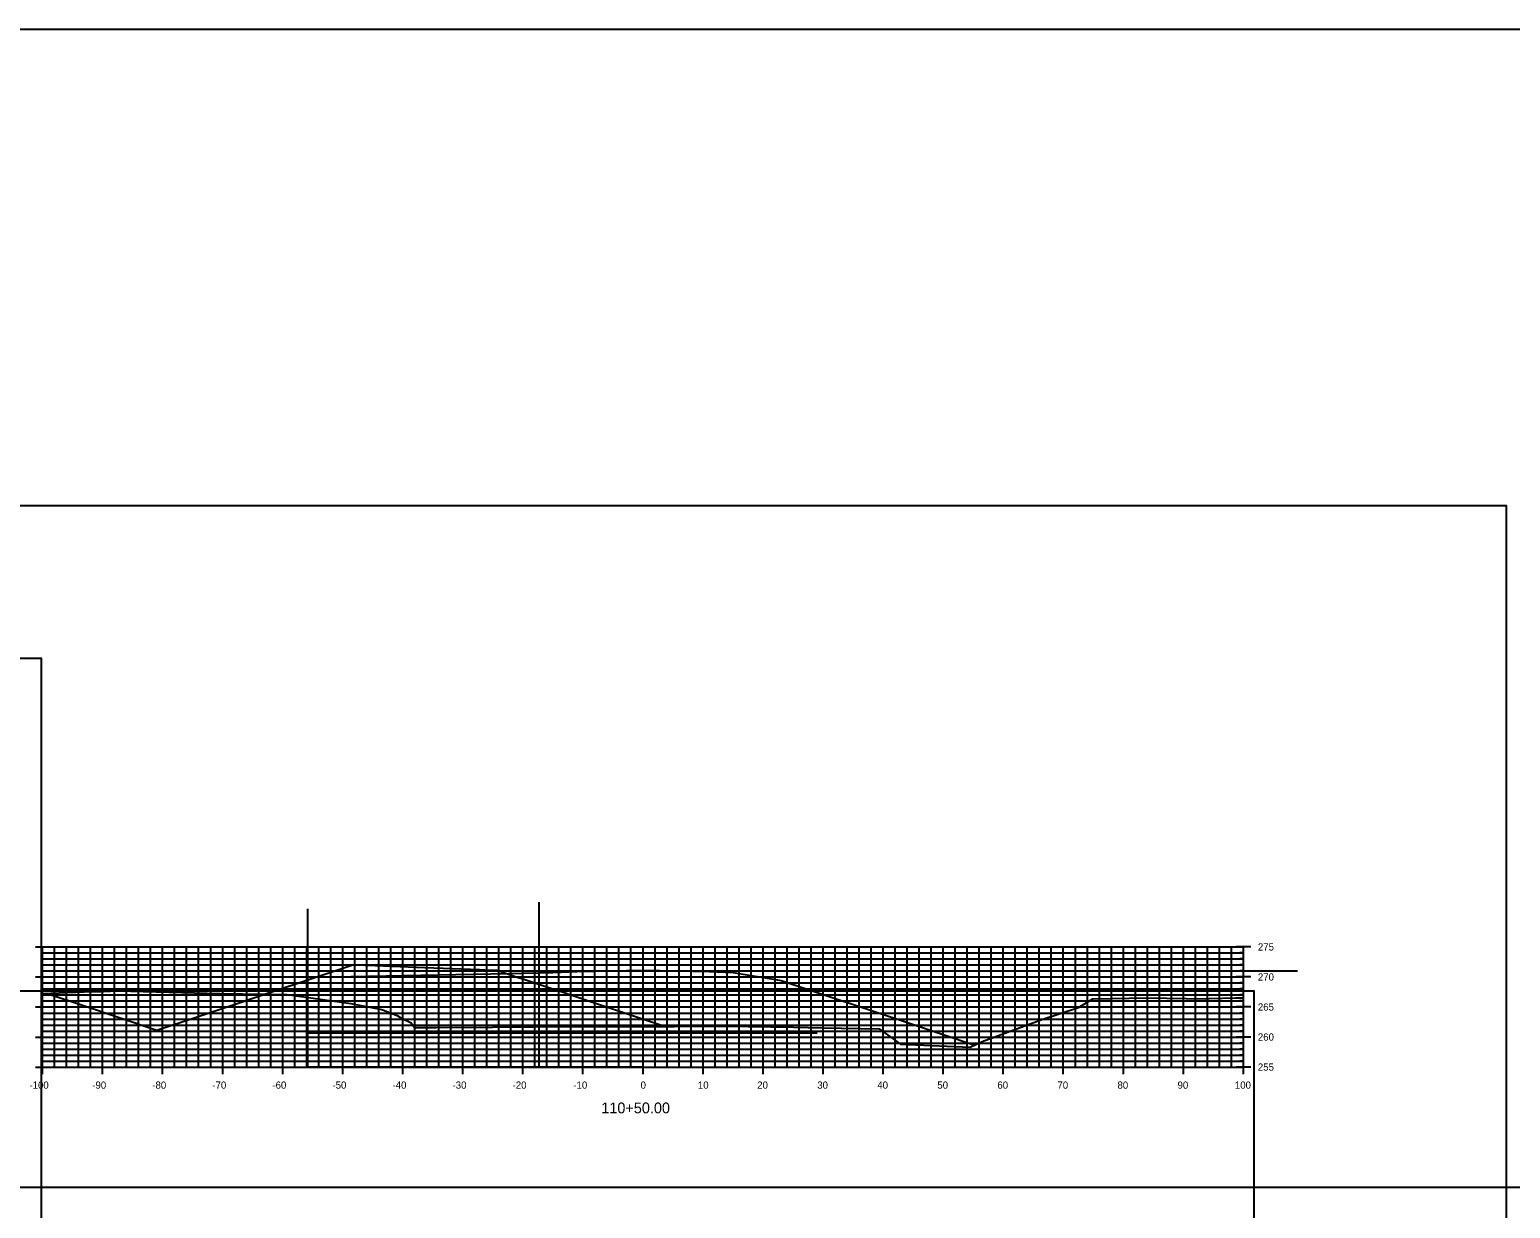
# Model space of a CAD drawing. Extents: x 1661012 to 1662122, y 670053 to 671852.
# Drawn here: x 1661390.7 to 1661637.3, y 671645.4 to 671841.6 of the extents above; entities that cross this region are included whole.
import ezdxf

# ---------------------------------------------------------------- set-up
doc = ezdxf.new("R2010")
doc.units = 0
for name, color, linetype in [('R_Barrier Wall', 7, 'Continuous'), ('R_Concrete', 7, 'Continuous'), ('R_Concrete Hidden', 7, 'Continuous'), ('R_Erosion', 7, 'Continuous'), ('R_Exist Surface', 7, 'Continuous'), ('R_Proposed Road', 7, 'Continuous'), ('R_ROW Annot', 7, 'Continuous')]:
    doc.layers.add(name, color=color, linetype=linetype)

msp = doc.modelspace()

# ---------------------------------------------------------------- linework, layer by layer
at = {"layer": 'R_Barrier Wall'}
for p, q in [((1661392.85, 671684.92), (1661601.83, 671684.92)), ((1661436.85, 671674.62), (1661521.85, 671674.54))]:
    msp.add_line(p, q, dxfattribs=at)
for points in [[(1661492.85, 671668.92), (1661437.01, 671668.92), (1661437.01, 671695.25)], [(1661492.85, 671668.92), (1661475.53, 671668.92), (1661475.53, 671696.39)]]:
    msp.add_lwpolyline(points, dxfattribs=at)
at = {"layer": 'R_Concrete'}
for p, q in [((1661391.65, 671688.92), (1661394.05, 671688.92)), ((1661392.85, 671688.92), (1661592.85, 671688.92)), ((1661392.85, 671668.92), (1661392.85, 671688.92)), ((1661392.85, 671687.92), (1661592.85, 671687.92)), ((1661392.85, 671687.92), (1661393.45, 671687.92)), ((1661394.85, 671668.92), (1661394.85, 671688.92)), ((1661396.85, 671668.92), (1661396.85, 671688.92)), ((1661398.85, 671668.92), (1661398.85, 671688.92)), ((1661400.85, 671668.92), (1661400.85, 671688.92)), ((1661402.85, 671668.92), (1661402.85, 671688.92)), ((1661404.85, 671668.92), (1661404.85, 671688.92)), ((1661406.85, 671668.92), (1661406.85, 671688.92)), ((1661408.85, 671668.92), (1661408.85, 671688.92)), ((1661410.85, 671668.92), (1661410.85, 671688.92)), ((1661412.85, 671668.92), (1661412.85, 671688.92)), ((1661414.85, 671668.92), (1661414.85, 671688.92)), ((1661416.85, 671668.92), (1661416.85, 671688.92)), ((1661418.85, 671668.92), (1661418.85, 671688.92)), ((1661420.85, 671668.92), (1661420.85, 671688.92)), ((1661422.85, 671668.92), (1661422.85, 671688.92)), ((1661424.85, 671668.92), (1661424.85, 671688.92)), ((1661426.85, 671668.92), (1661426.85, 671688.92)), ((1661428.85, 671668.92), (1661428.85, 671688.92)), ((1661430.85, 671668.92), (1661430.85, 671688.92)), ((1661432.85, 671668.92), (1661432.85, 671688.92)), ((1661434.85, 671668.92), (1661434.85, 671688.92)), ((1661436.85, 671668.92), (1661436.85, 671688.92)), ((1661438.85, 671668.92), (1661438.85, 671688.92)), ((1661440.85, 671668.92), (1661440.85, 671688.92)), ((1661442.85, 671668.92), (1661442.85, 671688.92)), ((1661444.85, 671668.92), (1661444.85, 671688.92)), ((1661446.85, 671668.92), (1661446.85, 671688.92)), ((1661448.85, 671668.92), (1661448.85, 671688.92)), ((1661450.85, 671668.92), (1661450.85, 671688.92)), ((1661452.85, 671668.92), (1661452.85, 671688.92)), ((1661454.85, 671668.92), (1661454.85, 671688.92)), ((1661456.85, 671668.92), (1661456.85, 671688.92)), ((1661458.85, 671668.92), (1661458.85, 671688.92)), ((1661460.85, 671668.92), (1661460.85, 671688.92)), ((1661462.85, 671668.92), (1661462.85, 671688.92)), ((1661464.85, 671668.92), (1661464.85, 671688.92)), ((1661466.85, 671668.92), (1661466.85, 671688.92)), ((1661468.85, 671668.92), (1661468.85, 671688.92)), ((1661470.85, 671668.92), (1661470.85, 671688.92)), ((1661472.85, 671668.92), (1661472.85, 671688.92)), ((1661474.85, 671668.92), (1661474.85, 671688.92)), ((1661476.85, 671668.92), (1661476.85, 671688.92)), ((1661478.85, 671668.92), (1661478.85, 671688.92)), ((1661480.85, 671668.92), (1661480.85, 671688.92)), ((1661482.85, 671668.92), (1661482.85, 671688.92)), ((1661484.85, 671668.92), (1661484.85, 671688.92)), ((1661486.85, 671668.92), (1661486.85, 671688.92)), ((1661488.85, 671668.92), (1661488.85, 671688.92)), ((1661490.85, 671668.92), (1661490.85, 671688.92)), ((1661492.85, 671668.92), (1661492.85, 671688.92)), ((1661494.85, 671668.92), (1661494.85, 671688.92)), ((1661496.85, 671668.92), (1661496.85, 671688.92)), ((1661498.85, 671668.92), (1661498.85, 671688.92)), ((1661500.85, 671668.92), (1661500.85, 671688.92)), ((1661502.85, 671668.92), (1661502.85, 671688.92)), ((1661504.85, 671668.92), (1661504.85, 671688.92)), ((1661506.85, 671668.92), (1661506.85, 671688.92)), ((1661508.85, 671668.92), (1661508.85, 671688.92)), ((1661510.85, 671668.92), (1661510.85, 671688.92)), ((1661512.85, 671668.92), (1661512.85, 671688.92)), ((1661514.85, 671668.92), (1661514.85, 671688.92)), ((1661516.85, 671668.92), (1661516.85, 671688.92)), ((1661518.85, 671668.92), (1661518.85, 671688.92)), ((1661520.85, 671668.92), (1661520.85, 671688.92)), ((1661522.85, 671668.92), (1661522.85, 671688.92)), ((1661524.85, 671668.92), (1661524.85, 671688.92)), ((1661526.85, 671668.92), (1661526.85, 671688.92)), ((1661528.85, 671668.92), (1661528.85, 671688.92)), ((1661530.85, 671668.92), (1661530.85, 671688.92)), ((1661532.85, 671668.92), (1661532.85, 671688.92)), ((1661534.85, 671668.92), (1661534.85, 671688.92)), ((1661536.85, 671668.92), (1661536.85, 671688.92)), ((1661538.85, 671668.92), (1661538.85, 671688.92)), ((1661540.85, 671668.92), (1661540.85, 671688.92)), ((1661542.85, 671668.92), (1661542.85, 671688.92)), ((1661544.85, 671668.92), (1661544.85, 671688.92)), ((1661546.85, 671668.92), (1661546.85, 671688.92)), ((1661548.85, 671668.92), (1661548.85, 671688.92)), ((1661550.85, 671668.92), (1661550.85, 671688.92)), ((1661552.85, 671668.92), (1661552.85, 671688.92)), ((1661554.85, 671668.92), (1661554.85, 671688.92)), ((1661556.85, 671668.92), (1661556.85, 671688.92)), ((1661558.85, 671668.92), (1661558.85, 671688.92)), ((1661560.85, 671668.92), (1661560.85, 671688.92)), ((1661562.85, 671668.92), (1661562.85, 671688.92)), ((1661564.85, 671668.92), (1661564.85, 671688.92)), ((1661566.85, 671668.92), (1661566.85, 671688.92)), ((1661568.85, 671668.92), (1661568.85, 671688.92)), ((1661570.85, 671668.92), (1661570.85, 671688.92)), ((1661572.85, 671668.92), (1661572.85, 671688.92)), ((1661574.85, 671668.92), (1661574.85, 671688.92)), ((1661576.85, 671668.92), (1661576.85, 671688.92)), ((1661578.85, 671668.92), (1661578.85, 671688.92)), ((1661580.85, 671668.92), (1661580.85, 671688.92)), ((1661582.85, 671668.92), (1661582.85, 671688.92)), ((1661584.85, 671668.92), (1661584.85, 671688.92)), ((1661586.85, 671668.92), (1661586.85, 671688.92)), ((1661588.85, 671668.92), (1661588.85, 671688.92)), ((1661590.85, 671668.92), (1661590.85, 671688.92)), ((1661594.05, 671688.92), (1661591.65, 671688.92)), ((1661592.85, 671687.92), (1661592.25, 671687.92)), ((1661592.85, 671668.92), (1661592.85, 671688.92)), ((1661392.85, 671686.92), (1661592.85, 671686.92)), ((1661392.85, 671686.92), (1661393.45, 671686.92)), ((1661392.85, 671685.92), (1661592.85, 671685.92)), ((1661392.85, 671685.92), (1661393.45, 671685.92)), ((1661392.85, 671684.92), (1661592.85, 671684.92)), ((1661392.85, 671684.92), (1661393.45, 671684.92)), ((1661592.85, 671686.92), (1661592.25, 671686.92)), ((1661592.85, 671685.92), (1661592.25, 671685.92)), ((1661592.85, 671684.92), (1661592.25, 671684.92)), ((1661391.65, 671683.92), (1661394.05, 671683.92)), ((1661392.85, 671683.92), (1661592.85, 671683.92)), ((1661392.85, 671682.92), (1661592.85, 671682.92)), ((1661392.85, 671682.92), (1661393.45, 671682.92)), ((1661594.05, 671683.92), (1661591.65, 671683.92)), ((1661592.85, 671682.92), (1661592.25, 671682.92)), ((1661392.85, 671681.92), (1661592.85, 671681.92)), ((1661392.85, 671681.92), (1661393.45, 671681.92)), ((1661392.85, 671680.92), (1661592.85, 671680.92)), ((1661392.85, 671680.92), (1661393.45, 671680.92)), ((1661392.85, 671679.92), (1661592.85, 671679.92)), ((1661392.85, 671679.92), (1661393.45, 671679.92)), ((1661592.85, 671681.92), (1661592.25, 671681.92)), ((1661592.85, 671680.92), (1661592.25, 671680.92)), ((1661592.85, 671679.92), (1661592.25, 671679.92)), ((1661391.65, 671678.92), (1661394.05, 671678.92)), ((1661392.85, 671678.92), (1661592.85, 671678.92)), ((1661392.85, 671677.92), (1661592.85, 671677.92)), ((1661392.85, 671677.92), (1661393.45, 671677.92)), ((1661594.05, 671678.92), (1661591.65, 671678.92)), ((1661592.85, 671677.92), (1661592.25, 671677.92)), ((1661392.85, 671676.92), (1661592.85, 671676.92)), ((1661392.85, 671676.92), (1661393.45, 671676.92)), ((1661392.85, 671675.92), (1661592.85, 671675.92)), ((1661392.85, 671675.92), (1661393.45, 671675.92)), ((1661392.85, 671674.92), (1661592.85, 671674.92)), ((1661392.85, 671674.92), (1661393.45, 671674.92)), ((1661592.85, 671676.92), (1661592.25, 671676.92)), ((1661592.85, 671675.92), (1661592.25, 671675.92)), ((1661592.85, 671674.92), (1661592.25, 671674.92)), ((1661391.65, 671673.92), (1661394.05, 671673.92)), ((1661392.85, 671673.92), (1661592.85, 671673.92)), ((1661392.85, 671672.92), (1661592.85, 671672.92)), ((1661392.85, 671672.92), (1661393.45, 671672.92)), ((1661594.05, 671673.92), (1661591.65, 671673.92)), ((1661592.85, 671672.92), (1661592.25, 671672.92)), ((1661392.85, 671671.92), (1661592.85, 671671.92)), ((1661392.85, 671671.92), (1661393.45, 671671.92)), ((1661392.85, 671670.92), (1661592.85, 671670.92)), ((1661392.85, 671670.92), (1661393.45, 671670.92)), ((1661392.85, 671667.72), (1661392.85, 671670.12)), ((1661392.85, 671669.92), (1661592.85, 671669.92)), ((1661392.85, 671669.92), (1661393.45, 671669.92)), ((1661402.85, 671667.72), (1661402.85, 671670.12)), ((1661412.85, 671667.72), (1661412.85, 671670.12)), ((1661422.85, 671667.72), (1661422.85, 671670.12)), ((1661432.85, 671667.72), (1661432.85, 671670.12)), ((1661442.85, 671667.72), (1661442.85, 671670.12)), ((1661452.85, 671667.72), (1661452.85, 671670.12)), ((1661462.85, 671667.72), (1661462.85, 671670.12)), ((1661472.85, 671667.72), (1661472.85, 671670.12)), ((1661482.85, 671667.72), (1661482.85, 671670.12)), ((1661492.85, 671667.72), (1661492.85, 671670.12)), ((1661502.85, 671667.72), (1661502.85, 671670.12)), ((1661512.85, 671667.72), (1661512.85, 671670.12)), ((1661522.85, 671667.72), (1661522.85, 671670.12)), ((1661532.85, 671667.72), (1661532.85, 671670.12)), ((1661542.85, 671667.72), (1661542.85, 671670.12)), ((1661552.85, 671667.72), (1661552.85, 671670.12)), ((1661562.85, 671667.72), (1661562.85, 671670.12)), ((1661572.85, 671667.72), (1661572.85, 671670.12)), ((1661582.85, 671667.72), (1661582.85, 671670.12)), ((1661592.85, 671671.92), (1661592.25, 671671.92)), ((1661592.85, 671670.92), (1661592.25, 671670.92)), ((1661592.85, 671669.92), (1661592.25, 671669.92)), ((1661592.85, 671667.72), (1661592.85, 671670.12)), ((1661391.65, 671668.92), (1661394.05, 671668.92)), ((1661392.85, 671668.92), (1661592.85, 671668.92)), ((1661394.85, 671668.92), (1661394.85, 671669.52)), ((1661396.85, 671668.92), (1661396.85, 671669.52)), ((1661398.85, 671668.92), (1661398.85, 671669.52)), ((1661400.85, 671668.92), (1661400.85, 671669.52)), ((1661404.85, 671668.92), (1661404.85, 671669.52)), ((1661406.85, 671668.92), (1661406.85, 671669.52)), ((1661408.85, 671668.92), (1661408.85, 671669.52)), ((1661410.85, 671668.92), (1661410.85, 671669.52)), ((1661414.85, 671668.92), (1661414.85, 671669.52)), ((1661416.85, 671668.92), (1661416.85, 671669.52)), ((1661418.85, 671668.92), (1661418.85, 671669.52)), ((1661420.85, 671668.92), (1661420.85, 671669.52)), ((1661424.85, 671668.92), (1661424.85, 671669.52)), ((1661426.85, 671668.92), (1661426.85, 671669.52)), ((1661428.85, 671668.92), (1661428.85, 671669.52)), ((1661430.85, 671668.92), (1661430.85, 671669.52)), ((1661434.85, 671668.92), (1661434.85, 671669.52)), ((1661436.85, 671668.92), (1661436.85, 671669.52)), ((1661438.85, 671668.92), (1661438.85, 671669.52)), ((1661440.85, 671668.92), (1661440.85, 671669.52)), ((1661444.85, 671668.92), (1661444.85, 671669.52)), ((1661446.85, 671668.92), (1661446.85, 671669.52)), ((1661448.85, 671668.92), (1661448.85, 671669.52)), ((1661450.85, 671668.92), (1661450.85, 671669.52)), ((1661454.85, 671668.92), (1661454.85, 671669.52)), ((1661456.85, 671668.92), (1661456.85, 671669.52)), ((1661458.85, 671668.92), (1661458.85, 671669.52)), ((1661460.85, 671668.92), (1661460.85, 671669.52)), ((1661464.85, 671668.92), (1661464.85, 671669.52)), ((1661466.85, 671668.92), (1661466.85, 671669.52)), ((1661468.85, 671668.92), (1661468.85, 671669.52)), ((1661470.85, 671668.92), (1661470.85, 671669.52)), ((1661474.85, 671668.92), (1661474.85, 671669.52)), ((1661476.85, 671668.92), (1661476.85, 671669.52)), ((1661478.85, 671668.92), (1661478.85, 671669.52)), ((1661480.85, 671668.92), (1661480.85, 671669.52)), ((1661484.85, 671668.92), (1661484.85, 671669.52)), ((1661486.85, 671668.92), (1661486.85, 671669.52)), ((1661488.85, 671668.92), (1661488.85, 671669.52)), ((1661490.85, 671668.92), (1661490.85, 671669.52)), ((1661494.85, 671668.92), (1661494.85, 671669.52)), ((1661496.85, 671668.92), (1661496.85, 671669.52)), ((1661498.85, 671668.92), (1661498.85, 671669.52)), ((1661500.85, 671668.92), (1661500.85, 671669.52)), ((1661504.85, 671668.92), (1661504.85, 671669.52)), ((1661506.85, 671668.92), (1661506.85, 671669.52)), ((1661508.85, 671668.92), (1661508.85, 671669.52)), ((1661510.85, 671668.92), (1661510.85, 671669.52)), ((1661514.85, 671668.92), (1661514.85, 671669.52)), ((1661516.85, 671668.92), (1661516.85, 671669.52)), ((1661518.85, 671668.92), (1661518.85, 671669.52)), ((1661520.85, 671668.92), (1661520.85, 671669.52)), ((1661524.85, 671668.92), (1661524.85, 671669.52)), ((1661526.85, 671668.92), (1661526.85, 671669.52)), ((1661528.85, 671668.92), (1661528.85, 671669.52)), ((1661530.85, 671668.92), (1661530.85, 671669.52)), ((1661534.85, 671668.92), (1661534.85, 671669.52)), ((1661536.85, 671668.92), (1661536.85, 671669.52)), ((1661538.85, 671668.92), (1661538.85, 671669.52)), ((1661540.85, 671668.92), (1661540.85, 671669.52)), ((1661544.85, 671668.92), (1661544.85, 671669.52)), ((1661546.85, 671668.92), (1661546.85, 671669.52)), ((1661548.85, 671668.92), (1661548.85, 671669.52)), ((1661550.85, 671668.92), (1661550.85, 671669.52)), ((1661554.85, 671668.92), (1661554.85, 671669.52)), ((1661556.85, 671668.92), (1661556.85, 671669.52)), ((1661558.85, 671668.92), (1661558.85, 671669.52)), ((1661560.85, 671668.92), (1661560.85, 671669.52)), ((1661564.85, 671668.92), (1661564.85, 671669.52)), ((1661566.85, 671668.92), (1661566.85, 671669.52)), ((1661568.85, 671668.92), (1661568.85, 671669.52)), ((1661570.85, 671668.92), (1661570.85, 671669.52)), ((1661574.85, 671668.92), (1661574.85, 671669.52)), ((1661576.85, 671668.92), (1661576.85, 671669.52)), ((1661578.85, 671668.92), (1661578.85, 671669.52)), ((1661580.85, 671668.92), (1661580.85, 671669.52)), ((1661584.85, 671668.92), (1661584.85, 671669.52)), ((1661586.85, 671668.92), (1661586.85, 671669.52)), ((1661588.85, 671668.92), (1661588.85, 671669.52)), ((1661590.85, 671668.92), (1661590.85, 671669.52)), ((1661594.05, 671668.92), (1661591.65, 671668.92))]:
    msp.add_line(p, q, dxfattribs=at)
at = {"layer": 'R_Erosion'}
msp.add_lwpolyline([(1661392.85, 671681.19), (1661401.18, 671681.48), (1661402.98, 671681.52), (1661405.35, 671681.62), (1661422.45, 671681.14), (1661433.59, 671680.99), (1661444.21, 671679.49), (1661449.34, 671678.51), (1661451.93, 671677.49), (1661452.53, 671677.11), (1661454.23, 671676.3), (1661454.79, 671675.52), (1661458.4, 671675.53), (1661467.76, 671675.57), (1661474.5, 671675.64), (1661480.23, 671675.67), (1661492.25, 671675.68), (1661493.33, 671675.66), (1661498.09, 671675.68), (1661506.6, 671675.73), (1661517.9, 671675.54), (1661522.79, 671675.43), (1661532.19, 671675.26), (1661535.72, 671672.71), (1661547.33, 671672.24), (1661549.35, 671673.17), (1661559.45, 671676.89), (1661565.35, 671678.85), (1661567.78, 671680.28), (1661567.78, 671680.28), (1661576.89, 671680.44), (1661586.51, 671680.29), (1661587.16, 671680.31), (1661591.53, 671680.46), (1661592.85, 671680.45)], dxfattribs=at)
at = {"layer": 'R_Exist Surface'}
for p, q in [((1661392.85, 671668.92), (1661392.85, 671688.92)), ((1661592.85, 671668.92), (1661592.85, 671688.92)), ((1661392.85, 671668.92), (1661592.85, 671668.92))]:
    msp.add_line(p, q, dxfattribs=at)
at = {"layer": 'R_Proposed Road'}
for points in [[(1661362.85, 671648.92), (1661722.85, 671648.92), (1661722.85, 671841.62), (1661362.85, 671841.62)], [(1661276.65, 671569.66), (1661636.65, 671569.66), (1661636.65, 671762.36), (1661276.65, 671762.36)], [(1661032.67, 671544.25), (1661392.67, 671544.25), (1661392.67, 671736.95), (1661032.67, 671736.95)], [(1661234.64, 671488.84), (1661594.64, 671488.84), (1661594.64, 671681.54), (1661234.64, 671681.54)]]:
    msp.add_lwpolyline(points, close=True, dxfattribs=at)
at = {"layer": 'R_ROW Annot'}
for points in [[(1661393.46, 671681.21), (1661400, 671679.04), (1661411.91, 671675.07), (1661418.59, 671677.3), (1661434.53, 671682.61), (1661435.85, 671683.05), (1661440.55, 671684.61), (1661441.34, 671684.88), (1661444.53, 671685.94), (1661444.89, 671685.93), (1661446.53, 671685.9), (1661448.26, 671685.83), (1661456.53, 671685.51), (1661465.63, 671685.15), (1661466.53, 671685.12), (1661468.37, 671685.04), (1661468.53, 671685.04), (1661472.25, 671683.8), (1661472.49, 671683.72), (1661478.35, 671681.76), (1661478.53, 671681.7), (1661479.05, 671681.53), (1661484.29, 671679.78), (1661496.61, 671675.67)], [(1661429.83, 671681.04), (1661438.35, 671683.88), (1661470.44, 671684.52), (1661477.85, 671684.67), (1661481.85, 671684.83), (1661492.85, 671685.05), (1661503.85, 671684.83), (1661507.85, 671684.67), (1661515.26, 671683.43), (1661515.85, 671683.33), (1661537.06, 671676.27), (1661548.09, 671672.59)]]:
    msp.add_lwpolyline(points, dxfattribs=at)

# ---------------------------------------------------------------- texts
at = {"layer": 'R_Concrete Hidden'}
for s, height, p in [('275', 1.2, (1661595.25, 671688.32)), ('270', 1.2, (1661595.25, 671683.32)), ('265', 1.2, (1661595.25, 671678.32)), ('260', 1.2, (1661595.25, 671673.32)), ('255', 1.2, (1661595.25, 671668.32)), ('-100', 1.2, (1661390.67, 671665.32)), ('-90', 1.2, (1661401.13, 671665.32)), ('-80', 1.2, (1661411.13, 671665.32)), ('-70', 1.2, (1661421.13, 671665.32)), ('-60', 1.2, (1661431.13, 671665.32)), ('-50', 1.2, (1661441.13, 671665.32)), ('-40', 1.2, (1661451.13, 671665.32)), ('-30', 1.2, (1661461.13, 671665.32)), ('-20', 1.2, (1661471.13, 671665.32)), ('-10', 1.2, (1661481.25, 671665.32)), ('0', 1.2, (1661492.45, 671665.32)), ('10', 1.2, (1661501.99, 671665.32)), ('20', 1.2, (1661511.87, 671665.32)), ('30', 1.2, (1661521.87, 671665.32)), ('40', 1.2, (1661531.87, 671665.32)), ('50', 1.2, (1661541.87, 671665.32)), ('60', 1.2, (1661551.87, 671665.32)), ('70', 1.2, (1661561.87, 671665.32)), ('80', 1.2, (1661571.87, 671665.32)), ('90', 1.2, (1661581.87, 671665.32)), ('100', 1.2, (1661591.42, 671665.32)), ('110+50.00', 1.8, (1661485.9, 671661.22))]:
    msp.add_text(s, height=height, dxfattribs=at).set_placement(p)
at = {"layer": 'R_Exist Surface'}
msp.add_text('-', height=0.0001, dxfattribs=at).set_placement((1661392.85, 671668.92))

doc.saveas('drawing.dxf')
